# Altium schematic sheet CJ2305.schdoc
size 127 x 101 mm
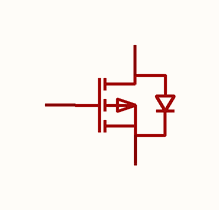
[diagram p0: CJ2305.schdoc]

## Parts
Q?  cj2305  [SOT-23-3_L2.9-W1.3-P1.90-LS2.4-BR]  (value not drawn)

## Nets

Not connected (* = marked no-connect by the designer): Q? 1(G) 2(S) 3(D)

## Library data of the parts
Q? = cj2305: 数量:1个P沟道;漏源电压(Vdss):12V;连续漏极电流(Id):4.1A;导通电阻(RDS(on)):90mΩ@1.8V;耗散功率(Pd):350mW;阈值电压(Vgs(th)):900mV;; Manufacturer: CJ(江苏长电/长晶); AddInBom: yes; ModelId: c62791f0466c4ae2a892c056b845b0ca; ModelName: SOT-23-3P_L2.9-W1.3-H1.0-LS2.4-P0.95; ModelTransform: 98.425,114.173,0,180,0,0,0.0005,-0.0005,0; Number: 1个P沟道; Drain to Source Voltage: 12V; Current - Continuous Drain(Id): 4.1A; Pd - Power Dissipation: 350mW; Gate Threshold Voltage (Vgs(th)): 900mV; Gate Charge(Qg): 7.8nC; Input Capacitance(Ciss): 740pF; Reverse Transfer Capacitance (Crss@Vds): 190pF; Type: P沟道; Output Capacitance(Coss): 290pF; Vgs: ±8V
